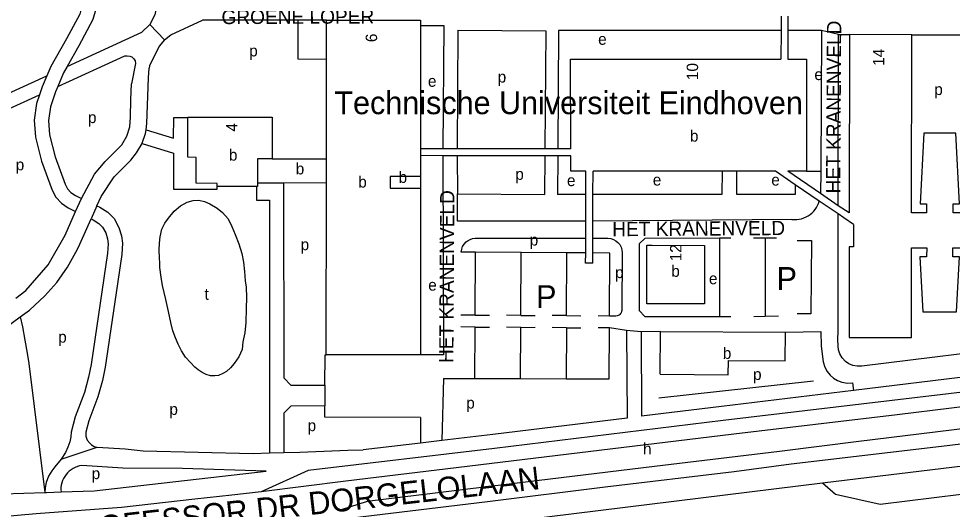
# Model space of a CAD drawing. Extents: x 161494 to 163033, y 383688 to 384862.
# Drawn here: x 161678.1 to 162005.1, y 384018.2 to 384190.1 of the extents above; entities that cross this region are included whole.
import ezdxf

# ---------------------------------------------------------------- set-up
doc = ezdxf.new("R2010")
doc.units = 0
for name, color, linetype in [('BLT_Basislijn', 7, 'Continuous'), ('BLT_Bebouwing', 7, 'Continuous'), ('BLT_Bebouwing_beschrifting', 7, 'Continuous'), ('BLT_Centroide', 7, 'Continuous'), ('BLT_Huisnummer', 7, 'Continuous'), ('BLT_Huisnummer_reeks', 7, 'Continuous'), ('BLT_Onderdoorgang_en_onderverdeling', 7, 'Continuous'), ('BLT_Onderverdeling_panden', 7, 'Continuous'), ('BLT_Straatnaam', 7, 'Continuous'), ('BLT_Straatnaam_hoofdweg', 7, 'Continuous'), ('BLT_Tekst_parkeren', 7, 'Continuous'), ('BLT_Vlakafsluiter', 7, 'Continuous')]:
    doc.layers.add(name, color=color, linetype=linetype)

msp = doc.modelspace()

# ---------------------------------------------------------------- linework, layer by layer
at = {"layer": 'BLT_Basislijn'}
for p, q in [((161776.01, 384189.5), (161742.47, 384189.5)), ((161785.89, 384189.5), (161776.01, 384189.5)), ((161831.96, 384186.07), (161831.69, 384144.45)), ((161831.96, 384186.07), (161862.7, 384185.87)), ((161862.7, 384185.87), (161862.43, 384144.44)), ((161867.2, 384185.91), (161866.93, 384144.43)), ((161990.93, 384184.45), (162010.71, 384184.45)), ((161831.68, 384142.07), (161831.77, 384128.65)), ((161862.42, 384142.05), (161862.33, 384128.44)), ((161866.92, 384142.04), (161866.83, 384128.42)), ((161954.09, 384136.59), (161959.03, 384136.59)), ((161959.03, 384136.59), (161958.99, 384128.82)), ((161831.77, 384128.65), (161862.33, 384128.44)), ((161876.77, 384128.42), (161866.83, 384128.42)), ((161697.95, 384122.55), (161700.02, 384127.11)), ((161705.46, 384124.49), (161703.41, 384119.93)), ((161948.96, 384119.73), (161879.21, 384119.14)), ((161897.5, 384113.23), (161895.49, 384111.22)), ((161897.5, 384113.23), (161923.54, 384113.29)), ((161923.54, 384113.29), (161923.54, 384085.7)), ((161923.54, 384113.29), (161927.56, 384113.29)), ((161935.54, 384113.32), (161939.57, 384113.32)), ((161939.57, 384113.32), (161943.6, 384113.32)), ((161939.57, 384113.32), (161939.57, 384085.84)), ((161837.95, 384086.19), (161838.09, 384108.24)), ((161854.08, 384108.19), (161838.09, 384108.24)), ((161853.97, 384086.11), (161854.08, 384108.19)), ((161870.14, 384108.06), (161854.08, 384108.19)), ((161895.49, 384111.22), (161895.45, 384096.7)), ((161869.99, 384086.02), (161870.14, 384108.06)), ((161876.71, 384108.01), (161870.14, 384108.06)), ((161885.18, 384107.96), (161879.17, 384108)), ((161885.06, 384085.9), (161885.18, 384107.96)), ((161895.45, 384096.7), (161895.42, 384087.78)), ((161837.95, 384086.19), (161832.96, 384086.22)), ((161837.95, 384086.19), (161842.96, 384086.18)), ((161853.97, 384086.11), (161848.97, 384086.17)), ((161853.97, 384086.11), (161858.97, 384086.08)), ((161869.99, 384086.02), (161864.98, 384086.05)), ((161869.99, 384086.02), (161875.01, 384085.96)), ((161885.06, 384085.9), (161881.02, 384085.94)), ((161895.42, 384087.78), (161897.41, 384085.78)), ((161897.41, 384085.78), (161923.54, 384085.7)), ((161923.54, 384085.7), (161927.56, 384085.7)), ((161935.57, 384085.72), (161939.57, 384085.84)), ((161939.57, 384085.84), (161944.19, 384085.98)), ((161837.94, 384082.01), (161832.93, 384082.05)), ((161837.85, 384064.03), (161837.94, 384082.01)), ((161837.94, 384082.01), (161842.95, 384082.01)), ((161854.01, 384081.91), (161848.94, 384081.98)), ((161853.87, 384063.96), (161854.01, 384081.91)), ((161854.01, 384081.91), (161858.96, 384081.93)), ((161869.99, 384081.8), (161865.01, 384081.89)), ((161869.99, 384081.8), (161869.92, 384063.88)), ((161869.99, 384081.8), (161874.99, 384081.78)), ((161885.02, 384081.74), (161881.03, 384081.75)), ((161884.91, 384063.85), (161885.02, 384081.74)), ((161891.02, 384080.81), (161885.02, 384081.74)), ((161891.02, 384080.81), (161891.27, 384050.16)), ((161896.13, 384080.38), (161891.02, 384080.81)), ((161902.9, 384080.43), (161896.13, 384080.38)), ((161896.13, 384080.38), (161896.26, 384050.77)), ((161826.88, 384064.05), (161826.28, 384042.25)), ((161826.88, 384064.05), (161837.85, 384064.03)), ((161837.85, 384064.03), (161853.87, 384063.96)), ((161853.87, 384063.96), (161869.92, 384063.88)), ((161869.92, 384063.88), (161884.91, 384063.85)), ((161902.34, 384057.25), (161956.47, 384063.18)), ((162016.53, 384065.35), (161970.53, 384059.79)), ((161785.32, 384061.71), (161785.32, 384054.46)), ((161970.53, 384059.79), (161924.28, 384054.21)), ((162015.41, 384059.99), (161924.88, 384049.24)), ((161924.28, 384054.21), (161896.26, 384050.77)), ((161818.78, 384050.39), (161818.78, 384041.36)), ((161891.27, 384050.16), (161844.16, 384044.38)), ((161924.88, 384049.24), (161844.76, 384039.42)), ((161844.16, 384044.38), (161826.28, 384042.25)), ((161818.78, 384041.36), (161798.75, 384038.98)), ((161826.28, 384042.25), (161818.78, 384041.36)), ((162016.75, 384034.31), (161960.62, 384027.39)), ((161792.62, 384027.97), (161763.07, 384024.34)), ((161960.62, 384027.39), (161959.65, 384027.27)), ((161964.19, 384023.37), (161959.65, 384027.27)), ((161672.52, 384023.56), (161687.21, 384024.07)), ((161687.84, 384024.08), (161692.91, 384024.24))]:
    msp.add_line(p, q, dxfattribs=at)
for points in [[(161738.88, 384265.84), (161739.65, 384264.55), (161740, 384263.17), (161740.1, 384261.53), (161725.81, 384191.4), (161724.04, 384187.99)], [(161691.9, 384257.18), (161692.86, 384253.06), (161695.17, 384247.3), (161696.47, 384243.72), (161697.16, 384239.21), (161700.34, 384207.24), (161700.71, 384201.3), (161700.69, 384197.4), (161700.24, 384194.47), (161699.44, 384191.68), (161694.82, 384183.03), (161689.31, 384173.35), (161687.96, 384170.1)], [(161699.7, 384249.42), (161699.84, 384249.09), (161701.34, 384244.97), (161702.12, 384239.83), (161705.33, 384207.64), (161705.71, 384201.44), (161705.69, 384197.01), (161705.13, 384193.39), (161704.1, 384189.8), (161699.2, 384180.62), (161695.06, 384173.34)], [(161695.06, 384173.34), (161721.24, 384185.3), (161724.04, 384187.99)], [(161729.16, 384182.64), (161731.33, 384184.41), (161742.47, 384189.5)], [(161785.89, 384175.73), (161776.01, 384175.9), (161776.01, 384189.5)], [(161818.82, 384187.72), (161826.97, 384187.67), (161826.69, 384144.45)], [(161945.14, 384185.91), (161867.2, 384185.91)], [(161959.29, 384185.91), (161947.49, 384185.91)], [(161959.29, 384185.91), (161959.03, 384136.59)], [(161965.16, 384124.53), (161965.22, 384184.48)], [(161965.22, 384184.48), (161969.07, 384184.48)], [(161729.16, 384182.64), (161727.25, 384180.47), (161723.9, 384173.57), (161723.73, 384172.71)], [(161691.83, 384166.37), (161715.26, 384177.07), (161716.12, 384177.11), (161716.97, 384177), (161717.75, 384176.68)], [(161717.75, 384176.68), (161718.41, 384176.05), (161718.85, 384175.28), (161718.97, 384174.4), (161717.57, 384167.3)], [(161695.06, 384173.34), (161693.81, 384171.15), (161691.83, 384166.37)], [(161722.71, 384151.17), (161723.02, 384153.37), (161723.6, 384169.31), (161723.73, 384172.71)], [(161666.14, 384160.13), (161687.96, 384170.1)], [(161687.96, 384170.1), (161686.33, 384166.16), (161685.4, 384163.43)], [(161700.02, 384127.11), (161704.62, 384135.63), (161708.31, 384140.06), (161711.88, 384143.49), (161714.22, 384145.87), (161715.94, 384148.93), (161716.99, 384152.15), (161717.2, 384155.59), (161717.39, 384161.71), (161717.57, 384167.3)], [(161691.83, 384166.37), (161691.01, 384164.39), (161689.25, 384159.24), (161688.56, 384154.35), (161688.91, 384149.4), (161690.83, 384141.68), (161694.37, 384132.07), (161695.21, 384130.48), (161696.35, 384129.23), (161697.94, 384128.11), (161700.02, 384127.11)], [(161668.12, 384155.53), (161685.4, 384163.43)], [(161685.4, 384163.43), (161684.37, 384160.4), (161683.53, 384154.52), (161683.96, 384148.61), (161686.05, 384140.2), (161689.8, 384130.03), (161691.08, 384127.58), (161693.03, 384125.45), (161695.4, 384123.78), (161697.95, 384122.55)], [(161722.71, 384151.17), (161732.36, 384148.19), (161732.37, 384155.49), (161737.37, 384155.49)], [(161721.29, 384146.37), (161721.32, 384146.43), (161722.53, 384149.84), (161722.71, 384151.17)], [(161705.46, 384124.49), (161706.96, 384127.82), (161711.48, 384134.71), (161717.36, 384140.48), (161719.39, 384143.1), (161721.29, 384146.37)], [(161721.29, 384146.37), (161732.36, 384142.96), (161732.34, 384130.36), (161747.57, 384130.29), (161747.58, 384131.31)], [(161826.68, 384142.07), (161826.86, 384072.3), (161818.79, 384072.28)], [(161924.48, 384136.61), (161924.4, 384128.46), (161879.24, 384128.42)], [(161950.05, 384131.91), (161950.05, 384128.45), (161929.63, 384128.46), (161929.69, 384136.61)], [(161761.4, 384131.31), (161761.39, 384126.46), (161765.9, 384126.43), (161765.98, 384037.93)], [(161770.89, 384132.48), (161770.96, 384064.22), (161773.46, 384061.71), (161785.32, 384061.71)], [(161876.74, 384119.13), (161831.8, 384119.16), (161831.77, 384128.65)], [(161948.96, 384119.73), (161949.81, 384119.68), (161950.66, 384119.71), (161951.51, 384119.81), (161952.34, 384120), (161953.15, 384120.26), (161953.93, 384120.6), (161954.67, 384121.01), (161955.38, 384121.49), (161956.03, 384122.03), (161956.63, 384122.63), (161957.11, 384123.25), (161957.52, 384123.92), (161958, 384124.83), (161958.26, 384125.29), (161958.52, 384126.15)], [(161677.12, 384092.19), (161680.55, 384094.83), (161688.44, 384103.81), (161694.33, 384114.22), (161697.95, 384122.55)], [(161705.46, 384124.49), (161706.52, 384123.98), (161709.26, 384122.29), (161711.52, 384120.03), (161713.21, 384116.92), (161714.06, 384114.01), (161714.41, 384111.47), (161714.22, 384107.44), (161708.41, 384067.99), (161707.42, 384063.26), (161705.85, 384057.52), (161702.62, 384049.11), (161701.65, 384045.24), (161701.63, 384043.84), (161702.11, 384042.43), (161702.94, 384041.38), (161703.59, 384040.74), (161704.53, 384040.19), (161705.58, 384039.92)], [(161965.12, 384080.52), (161965.16, 384121.74)], [(161678.63, 384085.58), (161681.84, 384087.94), (161687.25, 384092.99), (161691.4, 384097.69), (161695.21, 384103.02), (161698.63, 384109.27), (161699.48, 384111.1), (161701.91, 384116.61), (161703.41, 384119.93)], [(161703.41, 384119.93), (161704.11, 384119.59), (161706.14, 384118.34), (161707.47, 384117.01), (161708.56, 384115.01), (161709.16, 384112.97), (161709.39, 384111.24), (161709.23, 384107.93), (161703.49, 384068.87), (161702.56, 384064.43), (161701.09, 384059.08), (161697.84, 384050.62), (161696.47, 384045.14), (161696.35, 384043.61), (161695.97, 384041.83), (161695.3, 384039.97), (161694.46, 384038.11), (161693, 384035.77)], [(161838.09, 384108.24), (161833.09, 384108.25), (161833.26, 384109.35), (161833.57, 384110.21), (161834.1, 384111.09), (161834.83, 384111.86), (161835.52, 384112.38), (161836.26, 384112.75), (161837.06, 384113), (161838, 384113.13), (161876.72, 384113.14)], [(161879.19, 384113.14), (161884.49, 384113.14), (161885.51, 384113.02), (161886.45, 384112.71), (161887.25, 384112.27), (161888.01, 384111.64), (161888.61, 384110.9), (161889.08, 384110.02), (161889.36, 384109.09), (161889.46, 384108.08), (161889.33, 384087.83), (161889.26, 384087.42), (161889.12, 384087.06), (161888.94, 384086.75), (161888.69, 384086.47), (161888.4, 384086.24), (161888.08, 384086.07), (161887.7, 384085.95), (161887.3, 384085.9), (161885.06, 384085.9)], [(161950.76, 384112.33), (161955.75, 384112.33), (161955.53, 384086.7), (161950.76, 384086.7)], [(162037.04, 384088.82), (162036.53, 384080.07), (162035.9, 384078.31), (162034.83, 384076.99), (162033.62, 384076.14), (162032.14, 384075.62), (161973.45, 384068.36), (161971.82, 384068.3), (161970.32, 384068.57), (161968.94, 384069.14), (161967.71, 384069.97), (161966.53, 384071.23), (161965.71, 384072.68), (161965.29, 384073.99), (161965.13, 384075.37), (161965.09, 384077.77), (161965.12, 384080.52)], [(161665.54, 384076.97), (161673.2, 384081.6), (161678.63, 384085.58)], [(161678.63, 384085.58), (161679.37, 384082.08), (161680.27, 384077.47), (161681.08, 384072.85), (161681.67, 384069.23), (161687.21, 384024.07)], [(161946.69, 384080.2), (161959.05, 384080.42), (161959.2, 384075.34), (161959.87, 384069.79), (161960.43, 384068.02), (161961.29, 384066.44), (161962.36, 384065.14), (161963.57, 384064.11), (161964.96, 384063.29), (161966.47, 384062.72), (161968.44, 384062.39), (161970.21, 384062.46), (161970.53, 384059.79)], [(161785.32, 384061.71), (161785.41, 384072.26), (161785.82, 384072.28)], [(162042.92, 384058.28), (161985.85, 384051.24), (161928.63, 384044.5)], [(161785.32, 384054.46), (161773.42, 384054.35), (161770.97, 384051.89), (161770.98, 384038.06)], [(161818.78, 384050.39), (161785.33, 384050.44), (161785.32, 384054.46)], [(162065, 384053.23), (161972.34, 384041.96), (161944.6, 384038.44)], [(162065.15, 384047.88), (162001.35, 384040.13), (161948.68, 384033.93)], [(161928.63, 384044.5), (161835.15, 384033.17), (161792.62, 384027.97)], [(161705.58, 384039.92), (161715.4, 384039.33), (161721.65, 384038.66), (161760.27, 384037.77), (161765.98, 384037.93)], [(161844.76, 384039.42), (161779.46, 384031.74), (161763.07, 384024.34)], [(161765.98, 384037.93), (161770.98, 384038.06)], [(161770.98, 384038.06), (161776.56, 384038.22), (161793.38, 384038.84), (161798.75, 384038.98)], [(161944.6, 384038.44), (161900.8, 384033.22), (161835.45, 384025.19)], [(161693, 384035.77), (161690.74, 384033.1), (161689.63, 384031.68), (161688.53, 384029.82), (161687.71, 384027.55), (161687.34, 384025.65), (161687.21, 384024.07)], [(161700.23, 384033.53), (161699.42, 384033.38), (161698.63, 384033.16), (161697.86, 384032.86), (161697.13, 384032.49), (161696.44, 384032.05), (161695.79, 384031.55), (161695.2, 384030.98), (161694.66, 384030.36), (161694.18, 384029.69), (161693.78, 384028.98), (161693.44, 384028.23), (161693.18, 384027.45), (161693, 384026.65), (161692.89, 384025.83), (161692.86, 384025.01), (161692.91, 384024.24)], [(161692.91, 384024.24), (161704.47, 384024.6), (161764.73, 384031.52), (161735.49, 384032.41), (161714.51, 384032.63), (161700.23, 384033.53)], [(161948.68, 384033.93), (161928.68, 384031.25), (161883.47, 384025.89), (161842.35, 384020.82)], [(161959.65, 384027.27), (161916.99, 384022.03), (161846.02, 384013.32)], [(161687.21, 384024.07), (161687.84, 384024.08)], [(161763.07, 384024.34), (161752.69, 384023.07), (161739.79, 384021.71)], [(161835.45, 384025.19), (161800.1, 384020.96), (161791.09, 384018)], [(162017.64, 384024.49), (161979.82, 384019.8), (161964.19, 384023.37)], [(161739.79, 384021.71), (161714.13, 384018.78), (161684.15, 384016.64), (161672.41, 384015.53)], [(161842.35, 384020.82), (161788.17, 384014.19)]]:
    msp.add_lwpolyline(points, dxfattribs=at)
msp.add_lwpolyline([(161745.28, 384064.99), (161743.75, 384065.38), (161742.33, 384066.11), (161740.94, 384067.03), (161739.75, 384067.99), (161738.22, 384069.6), (161736.49, 384071.52), (161735.07, 384073.64), (161733.95, 384075.98), (161732.95, 384078.25), (161732.03, 384080.7), (161731.34, 384083.58), (161730.57, 384087.43), (161729.61, 384091.65), (161728.5, 384096.53), (161727.96, 384099.53), (161727.5, 384102.87), (161727.54, 384104.37), (161727.42, 384106.29), (161727.31, 384109.01), (161727.38, 384111.4), (161727.61, 384113.62), (161728.27, 384116.27), (161729.27, 384118.39), (161730.57, 384120.23), (161732.53, 384122.65), (161734.8, 384124.49), (161737.1, 384125.8), (161739.25, 384126.41), (161741.21, 384126.45), (161743.13, 384126.03), (161745.02, 384125.19), (161747.55, 384123.73), (161749.47, 384122.15), (161751.51, 384120), (161752.77, 384117.23), (161753.93, 384114.51), (161755.16, 384111.13), (161756.19, 384107.78), (161756.85, 384104.75), (161757.12, 384101.48), (161757.38, 384098.18), (161757.73, 384096.03), (161757.85, 384092.34), (161757.77, 384088.5), (161757.61, 384083.66), (161757.27, 384080.01), (161756.65, 384076.9), (161756.31, 384074.21), (161755.19, 384071.56), (161753.58, 384069.22), (161752.24, 384067.76), (161750.82, 384066.49), (161749.55, 384065.76), (161748.09, 384065.11), (161746.74, 384064.92)], close=True, dxfattribs=at)
at = {"layer": 'BLT_Bebouwing'}
for p, q in [((161945.19, 384190.91), (161945.14, 384185.91)), ((161947.49, 384190.91), (161947.49, 384185.91)), ((161785.89, 384175.73), (161785.89, 384189.5)), ((161785.86, 384140.98), (161785.89, 384175.73)), ((161766.87, 384141.01), (161785.86, 384140.98)), ((161818.8, 384142.08), (161818.8, 384134.83)), ((161818.8, 384134.83), (161818.8, 384130.65)), ((161770.89, 384132.48), (161761.76, 384132.46)), ((161900, 384110.68), (161918.29, 384110.64)), ((161918.29, 384110.64), (161918.27, 384090.19)), ((161879.16, 384104.46), (161876.69, 384104.47)), ((161898.08, 384094.24), (161898.08, 384096.7)), ((161902.78, 384065.47), (161902.9, 384080.43)), ((161818.79, 384072.28), (161785.82, 384072.28))]:
    msp.add_line(p, q, dxfattribs=at)
for points in [[(161785.89, 384189.5), (161818.82, 384189.51), (161818.82, 384187.72)], [(161818.82, 384187.72), (161818.81, 384162.87)], [(161945.14, 384185.91), (161945.03, 384175.87)], [(161947.49, 384185.91), (161947.48, 384175.87)], [(161969.07, 384184.48), (161969.03, 384122.04)], [(161990.93, 384184.45), (161969.07, 384184.48)], [(162010.71, 384184.45), (162010.64, 384122.06), (162005.38, 384122.07), (162005.38, 384125.2), (162007.7, 384125.2), (162006.42, 384149.99), (161995.16, 384149.99), (161993.82, 384125.21), (161996.14, 384125.21), (161996.14, 384122.06), (161990.88, 384122.07), (161990.93, 384184.45)], [(161871.44, 384144.43), (161871.41, 384175.88)], [(161871.41, 384175.88), (161945.03, 384175.87)], [(161947.48, 384175.87), (161954.08, 384175.87), (161954.09, 384136.59)], [(161818.81, 384162.87), (161818.8, 384144.46)], [(161747.58, 384131.31), (161747.58, 384132.38), (161740.24, 384132.39), (161740.28, 384141.49), (161737.35, 384141.5), (161737.37, 384155.49)], [(161737.37, 384155.49), (161737.37, 384155.59), (161766.89, 384155.56), (161766.87, 384141.01)], [(161826.69, 384144.45), (161818.8, 384144.46)], [(161831.69, 384144.45), (161826.69, 384144.45)], [(161862.43, 384144.44), (161831.69, 384144.45)], [(161866.93, 384144.43), (161862.43, 384144.44)], [(161871.44, 384144.43), (161866.93, 384144.43)], [(161826.68, 384142.07), (161818.8, 384142.08)], [(161831.68, 384142.07), (161826.68, 384142.07)], [(161862.42, 384142.05), (161831.68, 384142.07)], [(161866.92, 384142.04), (161862.42, 384142.05)], [(161871.44, 384142.04), (161866.92, 384142.04)], [(161871.45, 384136.6), (161871.44, 384142.04)], [(161876.8, 384136.6), (161871.45, 384136.6)], [(161876.77, 384128.42), (161876.8, 384136.6)], [(161879.24, 384128.42), (161879.27, 384136.6)], [(161924.48, 384136.61), (161899.58, 384136.61), (161879.27, 384136.6)], [(161929.69, 384136.61), (161924.48, 384136.61)], [(161943.15, 384136.6), (161929.69, 384136.61)], [(161950.05, 384131.91), (161943.15, 384136.6)], [(161958.99, 384128.82), (161947.55, 384136.6)], [(161954.09, 384136.59), (161947.55, 384136.6)], [(161761.4, 384131.31), (161747.58, 384131.31)], [(161761.76, 384132.46), (161761.77, 384131.31), (161761.4, 384131.31)], [(161785.86, 384132.52), (161770.89, 384132.48)], [(161785.82, 384072.28), (161785.86, 384132.52)], [(161958.52, 384126.15), (161950.05, 384131.91)], [(161818.8, 384130.65), (161818.8, 384124.57)], [(161876.74, 384119.13), (161876.77, 384128.42)], [(161879.21, 384119.14), (161879.24, 384128.42)], [(161965.16, 384124.53), (161958.99, 384128.82)], [(161818.8, 384124.57), (161818.79, 384111.82)], [(161965.16, 384121.74), (161958.52, 384126.15)], [(161969.03, 384122.04), (161965.16, 384124.53)], [(161970.56, 384117.96), (161967.08, 384120.33), (161965.16, 384121.74)], [(161876.72, 384113.14), (161876.74, 384119.13)], [(161879.19, 384113.14), (161879.21, 384119.14)], [(161970.56, 384117.96), (161970.55, 384110.1), (161969.01, 384110.1), (161968.99, 384078.41), (161990.85, 384078.38), (161990.87, 384109.77), (161996.16, 384109.78), (161996.13, 384106.62), (161993.8, 384106.62), (161994.79, 384087.31), (162006.64, 384087.31), (162007.69, 384106.6), (162005.36, 384106.61), (162005.37, 384109.74), (162010.59, 384109.74), (162010.6, 384078.36), (162032.45, 384078.34)], [(161818.79, 384111.82), (161818.79, 384072.28)], [(161876.71, 384108.01), (161876.72, 384113.14)], [(161879.17, 384108), (161879.19, 384113.14)], [(161898.08, 384096.7), (161898.08, 384110.67), (161900, 384110.68)], [(161876.69, 384104.47), (161876.71, 384108.01)], [(161879.16, 384104.46), (161879.17, 384108)], [(161918.27, 384090.19), (161900, 384090.18), (161898.08, 384090.2), (161898.08, 384094.24)], [(161902.9, 384080.43), (161946.69, 384080.2)], [(161946.62, 384070.23), (161946.69, 384080.2)], [(161902.78, 384065.47), (161926.67, 384065.34), (161926.71, 384070.33), (161946.62, 384070.23)]]:
    msp.add_lwpolyline(points, dxfattribs=at)
at = {"layer": 'BLT_Onderdoorgang_en_onderverdeling'}
for p, q in [((161761.78, 384141.02), (161761.76, 384132.46)), ((161766.87, 384141.01), (161761.78, 384141.02)), ((161785.86, 384132.52), (161785.86, 384140.98))]:
    msp.add_line(p, q, dxfattribs=at)
msp.add_lwpolyline([(161818.8, 384134.83), (161808.22, 384134.83), (161808.22, 384130.65), (161818.8, 384130.65)], dxfattribs=at)
at = {"layer": 'BLT_Onderverdeling_panden'}
msp.add_line((161818.8, 384144.46), (161818.8, 384142.08), dxfattribs=at)
at = {"layer": 'BLT_Vlakafsluiter'}
for p, q in [((161724.04, 384187.99), (161729.16, 384182.64)), ((161965.22, 384184.48), (161959.29, 384185.91)), ((161693, 384035.77), (161705.58, 384039.92))]:
    msp.add_line(p, q, dxfattribs=at)

# ---------------------------------------------------------------- texts
at = {"layer": 'BLT_Bebouwing_beschrifting'}
msp.add_text('Technische Universiteit Eindhoven', height=8, dxfattribs=at).set_placement((161788.67, 384156.61))
at = {"layer": 'BLT_Centroide'}
for s, p in [('e', (161881.07, 384180.93)), ('p', (161758.82, 384176.86)), ('p', (161845.89, 384167.7)), ('e', (161956.82, 384168.57)), ('e', (161821.44, 384166.23)), ('p', (161998.83, 384163.33)), ('p', (161702.35, 384153.5)), ('b', (161913.23, 384147.02)), ('b', (161751.72, 384140.35)), ('p', (161677.04, 384136.94)), ('b', (161775.13, 384135.52)), ('b', (161797.04, 384130.91)), ('b', (161811.17, 384132.55)), ('p', (161852.05, 384133.61)), ('e', (161870.15, 384131.41)), ('e', (161900.22, 384131.61)), ('e', (161941.73, 384131.61)), ('p', (161776.85, 384108.95)), ('p', (161857.11, 384110.59)), ('p', (161887.01, 384099.19)), ('b', (161906.7, 384099.63)), ('e', (161919.89, 384097.03)), ('t', (161743.19, 384091.57)), ('e', (161821.55, 384094.78)), ('p', (161691.91, 384076.58)), ('b', (161924.74, 384070.88)), ('p', (161935.34, 384063.49)), ('p', (161834.87, 384053.47)), ('p', (161730.88, 384051.25)), ('p', (161779.3, 384045.55)), ('h', (161896.8, 384037.38)), ('p', (161703.65, 384028.74))]:
    msp.add_text(s, height=4, dxfattribs=at).set_placement(p)
at = {"layer": 'BLT_Huisnummer'}
for s, rotation, p in [('6', 89.6523, (161803.62, 384181.85)), ('4', 89.6523, (161754.71, 384150.52)), ('12', 90.1214, (161910.26, 384105.08))]:
    msp.add_text(s, height=4, rotation=rotation, dxfattribs=at).set_placement(p)
at = {"layer": 'BLT_Huisnummer_reeks'}
for s, p in [('14', (161981.32, 384173.57)), ('10', (161916.09, 384168.58))]:
    msp.add_text(s, height=4, rotation=90.1214, dxfattribs=at).set_placement(p)
at = {"layer": 'BLT_Straatnaam'}
for s, height, rotation, p in [('GROENE LOPER', 5, 0.2472, (161749.12, 384188.17)), ('HET KRANENVELD', 4.9999, 89.6664, (161965.88, 384128.83)), ('HET KRANENVELD', 4.9999, 89.6664, (161830.35, 384069.41)), ('HET KRANENVELD', 5, 0.4105, (161886.01, 384113.83))]:
    msp.add_text(s, height=height, rotation=rotation, dxfattribs=at).set_placement(p)
at = {"layer": 'BLT_Straatnaam_hoofdweg'}
msp.add_text('PROFESSOR DR DORGELOLAAN', height=8, rotation=6.4466, dxfattribs=at).set_placement((161692.04, 384006.18))
at = {"layer": 'BLT_Tekst_parkeren'}
for p in [(161943.58, 384095.04), (161859.34, 384088.7)]:
    msp.add_text('P', height=8, dxfattribs=at).set_placement(p)

doc.saveas('drawing.dxf')
